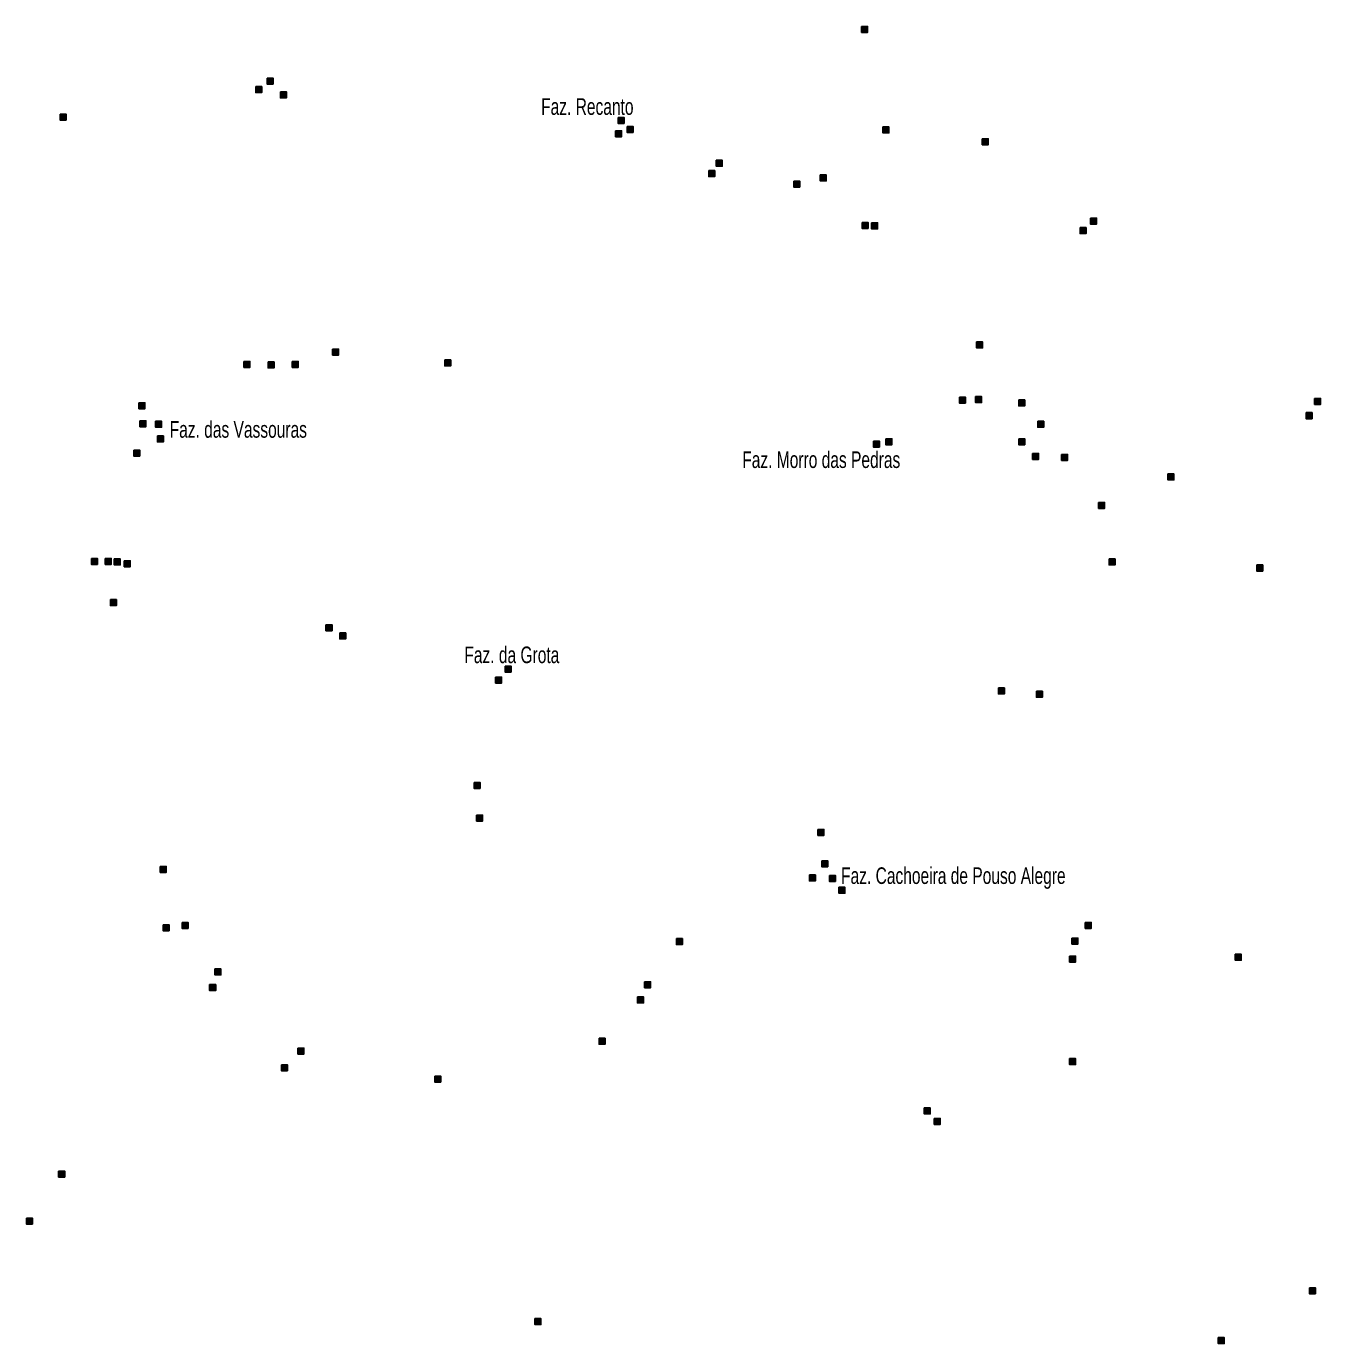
# Model space of a CAD drawing. Extents: x 447.8 to 473.9, y 7733.1 to 7760.8.
# Drawn here: x 461.4 to 467.64, y 7733.67 to 7740.03 of the extents above; entities that cross this region are included whole.
import ezdxf
from ezdxf.enums import TextEntityAlignment as Align

# ---------------------------------------------------------------- set-up
doc = ezdxf.new("R2010")
doc.units = 0
doc.header["$LTSCALE"] = 0.032
doc.layers.add('2', color=7, linetype='Continuous', lineweight=25)
doc.layers.add('61', color=7, linetype='Continuous')

msp = doc.modelspace()

# ---------------------------------------------------------------- hatches: boundary and pattern name
at = {"layer": '2'}
for points in [[(465.4271, 7740.0274), (465.4561, 7740.0274), (465.4561, 7739.9984), (465.4271, 7739.9984)], [(462.5065, 7739.7367), (462.5355, 7739.7367), (462.5355, 7739.7077), (462.5065, 7739.7077)], [(462.5615, 7739.7779), (462.5905, 7739.7779), (462.5905, 7739.7489), (462.5615, 7739.7489)], [(462.6256, 7739.7116), (462.6546, 7739.7116), (462.6546, 7739.6826), (462.6256, 7739.6826)], [(461.5635, 7739.604), (461.5925, 7739.604), (461.5925, 7739.575), (461.5635, 7739.575)], [(464.2529, 7739.588), (464.2819, 7739.588), (464.2819, 7739.559), (464.2529, 7739.559)], [(464.2964, 7739.5445), (464.3254, 7739.5445), (464.3254, 7739.5155), (464.2964, 7739.5155)], [(465.5301, 7739.5422), (465.5591, 7739.5422), (465.5591, 7739.5132), (465.5301, 7739.5132)], [(464.2415, 7739.5239), (464.2705, 7739.5239), (464.2705, 7739.4949), (464.2415, 7739.4949)], [(466.0085, 7739.485), (466.0375, 7739.485), (466.0375, 7739.456), (466.0085, 7739.456)], [(464.7267, 7739.382), (464.7557, 7739.382), (464.7557, 7739.353), (464.7267, 7739.353)], [(464.6901, 7739.3316), (464.7191, 7739.3316), (464.7191, 7739.3026), (464.6901, 7739.3026)], [(465.228, 7739.311), (465.257, 7739.311), (465.257, 7739.282), (465.228, 7739.282)], [(465.0998, 7739.2813), (465.1288, 7739.2813), (465.1288, 7739.2523), (465.0998, 7739.2523)], [(466.5303, 7739.1027), (466.5593, 7739.1027), (466.5593, 7739.0737), (466.5303, 7739.0737)], [(465.4294, 7739.0821), (465.4584, 7739.0821), (465.4584, 7739.0531), (465.4294, 7739.0531)], [(465.4752, 7739.0798), (465.5042, 7739.0798), (465.5042, 7739.0508), (465.4752, 7739.0508)], [(466.48, 7739.0569), (466.509, 7739.0569), (466.509, 7739.0279), (466.48, 7739.0279)], [(462.8773, 7738.471), (462.9063, 7738.471), (462.9063, 7738.442), (462.8773, 7738.442)], [(465.981, 7738.5053), (466.01, 7738.5053), (466.01, 7738.4763), (465.981, 7738.4763)], [(462.4493, 7738.4115), (462.4783, 7738.4115), (462.4783, 7738.3825), (462.4493, 7738.3825)], [(462.566, 7738.4092), (462.595, 7738.4092), (462.595, 7738.3802), (462.566, 7738.3802)], [(462.6828, 7738.4115), (462.7118, 7738.4115), (462.7118, 7738.3825), (462.6828, 7738.3825)], [(463.4175, 7738.4184), (463.4465, 7738.4184), (463.4465, 7738.3894), (463.4175, 7738.3894)], [(461.9435, 7738.2124), (461.9725, 7738.2124), (461.9725, 7738.1834), (461.9435, 7738.1834)], [(465.8986, 7738.2398), (465.9276, 7738.2398), (465.9276, 7738.2108), (465.8986, 7738.2108)], [(465.9764, 7738.2421), (466.0054, 7738.2421), (466.0054, 7738.2131), (465.9764, 7738.2131)], [(466.1847, 7738.2261), (466.2137, 7738.2261), (466.2137, 7738.1971), (466.1847, 7738.1971)], [(467.6107, 7738.233), (467.6397, 7738.233), (467.6397, 7738.204), (467.6107, 7738.204)], [(467.5695, 7738.1643), (467.5985, 7738.1643), (467.5985, 7738.1353), (467.5695, 7738.1353)], [(461.9481, 7738.1254), (461.9771, 7738.1254), (461.9771, 7738.0964), (461.9481, 7738.0964)], [(462.0236, 7738.1231), (462.0526, 7738.1231), (462.0526, 7738.0941), (462.0236, 7738.0941)], [(466.2763, 7738.1231), (466.3053, 7738.1231), (466.3053, 7738.0941), (466.2763, 7738.0941)], [(462.0327, 7738.0521), (462.0617, 7738.0521), (462.0617, 7738.0231), (462.0327, 7738.0231)], [(465.4843, 7738.027), (465.5133, 7738.027), (465.5133, 7737.998), (465.4843, 7737.998)], [(465.5438, 7738.0384), (465.5728, 7738.0384), (465.5728, 7738.0094), (465.5438, 7738.0094)], [(466.1847, 7738.0384), (466.2137, 7738.0384), (466.2137, 7738.0094), (466.1847, 7738.0094)], [(461.9183, 7737.9835), (461.9473, 7737.9835), (461.9473, 7737.9545), (461.9183, 7737.9545)], [(466.2511, 7737.9674), (466.2801, 7737.9674), (466.2801, 7737.9384), (466.2511, 7737.9384)], [(466.3907, 7737.9629), (466.4197, 7737.9629), (466.4197, 7737.9339), (466.3907, 7737.9339)], [(466.9034, 7737.869), (466.9324, 7737.869), (466.9324, 7737.84), (466.9034, 7737.84)], [(466.5693, 7737.7317), (466.5983, 7737.7317), (466.5983, 7737.7027), (466.5693, 7737.7027)], [(461.7146, 7737.4616), (461.7436, 7737.4616), (461.7436, 7737.4326), (461.7146, 7737.4326)], [(461.781, 7737.4616), (461.81, 7737.4616), (461.81, 7737.4326), (461.781, 7737.4326)], [(461.8245, 7737.4593), (461.8535, 7737.4593), (461.8535, 7737.4303), (461.8245, 7737.4303)], [(461.8725, 7737.4502), (461.9015, 7737.4502), (461.9015, 7737.4212), (461.8725, 7737.4212)], [(466.6196, 7737.4593), (466.6486, 7737.4593), (466.6486, 7737.4303), (466.6196, 7737.4303)], [(467.3314, 7737.4296), (467.3604, 7737.4296), (467.3604, 7737.4006), (467.3314, 7737.4006)], [(461.8061, 7737.2625), (461.8351, 7737.2625), (461.8351, 7737.2335), (461.8061, 7737.2335)], [(462.8453, 7737.1412), (462.8743, 7737.1412), (462.8743, 7737.1122), (462.8453, 7737.1122)], [(462.9117, 7737.1023), (462.9407, 7737.1023), (462.9407, 7737.0733), (462.9117, 7737.0733)], [(463.7082, 7736.942), (463.7372, 7736.942), (463.7372, 7736.913), (463.7082, 7736.913)], [(463.6624, 7736.8894), (463.6914, 7736.8894), (463.6914, 7736.8604), (463.6624, 7736.8604)], [(466.0863, 7736.8368), (466.1153, 7736.8368), (466.1153, 7736.8078), (466.0863, 7736.8078)], [(466.2694, 7736.8207), (466.2984, 7736.8207), (466.2984, 7736.7917), (466.2694, 7736.7917)], [(463.5594, 7736.3813), (463.5884, 7736.3813), (463.5884, 7736.3523), (463.5594, 7736.3523)], [(463.5709, 7736.2233), (463.5999, 7736.2233), (463.5999, 7736.1943), (463.5709, 7736.1943)], [(465.2165, 7736.1547), (465.2455, 7736.1547), (465.2455, 7736.1257), (465.2165, 7736.1257)], [(465.2349, 7736.0036), (465.2639, 7736.0036), (465.2639, 7735.9746), (465.2349, 7735.9746)], [(462.0465, 7735.9761), (462.0755, 7735.9761), (462.0755, 7735.9471), (462.0465, 7735.9471)], [(465.1753, 7735.9349), (465.2043, 7735.9349), (465.2043, 7735.9059), (465.1753, 7735.9059)], [(465.2715, 7735.9327), (465.3005, 7735.9327), (465.3005, 7735.9037), (465.2715, 7735.9037)], [(465.3173, 7735.8754), (465.3463, 7735.8754), (465.3463, 7735.8464), (465.3173, 7735.8464)], [(462.0602, 7735.6946), (462.0892, 7735.6946), (462.0892, 7735.6656), (462.0602, 7735.6656)], [(462.1518, 7735.7061), (462.1808, 7735.7061), (462.1808, 7735.6771), (462.1518, 7735.6771)], [(466.5052, 7735.7061), (466.5342, 7735.7061), (466.5342, 7735.6771), (466.5052, 7735.6771)], [(464.5345, 7735.6282), (464.5635, 7735.6282), (464.5635, 7735.5992), (464.5345, 7735.5992)], [(466.4411, 7735.6305), (466.4701, 7735.6305), (466.4701, 7735.6015), (466.4411, 7735.6015)], [(466.4296, 7735.5436), (466.4586, 7735.5436), (466.4586, 7735.5146), (466.4296, 7735.5146)], [(467.2284, 7735.5527), (467.2574, 7735.5527), (467.2574, 7735.5237), (467.2284, 7735.5237)], [(462.3097, 7735.4818), (462.3387, 7735.4818), (462.3387, 7735.4528), (462.3097, 7735.4528)], [(464.3811, 7735.42), (464.4101, 7735.42), (464.4101, 7735.391), (464.3811, 7735.391)], [(462.2845, 7735.4062), (462.3135, 7735.4062), (462.3135, 7735.3772), (462.2845, 7735.3772)], [(464.3468, 7735.3467), (464.3758, 7735.3467), (464.3758, 7735.3177), (464.3468, 7735.3177)], [(462.7102, 7735.0995), (462.7392, 7735.0995), (462.7392, 7735.0705), (462.7102, 7735.0705)], [(464.1614, 7735.1476), (464.1904, 7735.1476), (464.1904, 7735.1186), (464.1614, 7735.1186)], [(466.4296, 7735.0492), (466.4586, 7735.0492), (466.4586, 7735.0202), (466.4296, 7735.0202)], [(462.6301, 7735.0194), (462.6591, 7735.0194), (462.6591, 7734.9904), (462.6301, 7734.9904)], [(463.3694, 7734.9645), (463.3984, 7734.9645), (463.3984, 7734.9355), (463.3694, 7734.9355)], [(465.7292, 7734.8111), (465.7582, 7734.8111), (465.7582, 7734.7821), (465.7292, 7734.7821)], [(465.7773, 7734.7608), (465.8063, 7734.7608), (465.8063, 7734.7318), (465.7773, 7734.7318)], [(461.5567, 7734.5067), (461.5857, 7734.5067), (461.5857, 7734.4777), (461.5567, 7734.4777)], [(461.401, 7734.2801), (461.43, 7734.2801), (461.43, 7734.2511), (461.401, 7734.2511)], [(467.5855, 7733.9436), (467.6145, 7733.9436), (467.6145, 7733.9146), (467.5855, 7733.9146)], [(463.8524, 7733.7949), (463.8814, 7733.7949), (463.8814, 7733.7659), (463.8524, 7733.7659)], [(467.146, 7733.7033), (467.175, 7733.7033), (467.175, 7733.6743), (467.146, 7733.6743)]]:
    msp.add_hatch(color=256, dxfattribs=at).paths.add_polyline_path(points)

# ---------------------------------------------------------------- linework, layer by layer
for points in [[(465.4271, 7740.0274), (465.4561, 7740.0274), (465.4561, 7739.9984), (465.4271, 7739.9984)], [(462.5065, 7739.7367), (462.5355, 7739.7367), (462.5355, 7739.7077), (462.5065, 7739.7077)], [(462.5615, 7739.7779), (462.5905, 7739.7779), (462.5905, 7739.7489), (462.5615, 7739.7489)], [(462.6256, 7739.7116), (462.6546, 7739.7116), (462.6546, 7739.6826), (462.6256, 7739.6826)], [(461.5635, 7739.604), (461.5925, 7739.604), (461.5925, 7739.575), (461.5635, 7739.575)], [(464.2529, 7739.588), (464.2819, 7739.588), (464.2819, 7739.559), (464.2529, 7739.559)], [(464.2964, 7739.5445), (464.3254, 7739.5445), (464.3254, 7739.5155), (464.2964, 7739.5155)], [(465.5301, 7739.5422), (465.5591, 7739.5422), (465.5591, 7739.5132), (465.5301, 7739.5132)], [(464.2415, 7739.5239), (464.2705, 7739.5239), (464.2705, 7739.4949), (464.2415, 7739.4949)], [(466.0085, 7739.485), (466.0375, 7739.485), (466.0375, 7739.456), (466.0085, 7739.456)], [(464.7267, 7739.382), (464.7557, 7739.382), (464.7557, 7739.353), (464.7267, 7739.353)], [(464.6901, 7739.3316), (464.7191, 7739.3316), (464.7191, 7739.3026), (464.6901, 7739.3026)], [(465.228, 7739.311), (465.257, 7739.311), (465.257, 7739.282), (465.228, 7739.282)], [(465.0998, 7739.2813), (465.1288, 7739.2813), (465.1288, 7739.2523), (465.0998, 7739.2523)], [(466.5303, 7739.1027), (466.5593, 7739.1027), (466.5593, 7739.0737), (466.5303, 7739.0737)], [(465.4294, 7739.0821), (465.4584, 7739.0821), (465.4584, 7739.0531), (465.4294, 7739.0531)], [(465.4752, 7739.0798), (465.5042, 7739.0798), (465.5042, 7739.0508), (465.4752, 7739.0508)], [(466.48, 7739.0569), (466.509, 7739.0569), (466.509, 7739.0279), (466.48, 7739.0279)], [(462.8773, 7738.471), (462.9063, 7738.471), (462.9063, 7738.442), (462.8773, 7738.442)], [(465.981, 7738.5053), (466.01, 7738.5053), (466.01, 7738.4763), (465.981, 7738.4763)], [(462.4493, 7738.4115), (462.4783, 7738.4115), (462.4783, 7738.3825), (462.4493, 7738.3825)], [(462.566, 7738.4092), (462.595, 7738.4092), (462.595, 7738.3802), (462.566, 7738.3802)], [(462.6828, 7738.4115), (462.7118, 7738.4115), (462.7118, 7738.3825), (462.6828, 7738.3825)], [(463.4175, 7738.4184), (463.4465, 7738.4184), (463.4465, 7738.3894), (463.4175, 7738.3894)], [(461.9435, 7738.2124), (461.9725, 7738.2124), (461.9725, 7738.1834), (461.9435, 7738.1834)], [(465.8986, 7738.2398), (465.9276, 7738.2398), (465.9276, 7738.2108), (465.8986, 7738.2108)], [(465.9764, 7738.2421), (466.0054, 7738.2421), (466.0054, 7738.2131), (465.9764, 7738.2131)], [(466.1847, 7738.2261), (466.2137, 7738.2261), (466.2137, 7738.1971), (466.1847, 7738.1971)], [(467.6107, 7738.233), (467.6397, 7738.233), (467.6397, 7738.204), (467.6107, 7738.204)], [(467.5695, 7738.1643), (467.5985, 7738.1643), (467.5985, 7738.1353), (467.5695, 7738.1353)], [(461.9481, 7738.1254), (461.9771, 7738.1254), (461.9771, 7738.0964), (461.9481, 7738.0964)], [(462.0236, 7738.1231), (462.0526, 7738.1231), (462.0526, 7738.0941), (462.0236, 7738.0941)], [(466.2763, 7738.1231), (466.3053, 7738.1231), (466.3053, 7738.0941), (466.2763, 7738.0941)], [(462.0327, 7738.0521), (462.0617, 7738.0521), (462.0617, 7738.0231), (462.0327, 7738.0231)], [(465.4843, 7738.027), (465.5133, 7738.027), (465.5133, 7737.998), (465.4843, 7737.998)], [(465.5438, 7738.0384), (465.5728, 7738.0384), (465.5728, 7738.0094), (465.5438, 7738.0094)], [(466.1847, 7738.0384), (466.2137, 7738.0384), (466.2137, 7738.0094), (466.1847, 7738.0094)], [(461.9183, 7737.9835), (461.9473, 7737.9835), (461.9473, 7737.9545), (461.9183, 7737.9545)], [(466.2511, 7737.9674), (466.2801, 7737.9674), (466.2801, 7737.9384), (466.2511, 7737.9384)], [(466.3907, 7737.9629), (466.4197, 7737.9629), (466.4197, 7737.9339), (466.3907, 7737.9339)], [(466.9034, 7737.869), (466.9324, 7737.869), (466.9324, 7737.84), (466.9034, 7737.84)], [(466.5693, 7737.7317), (466.5983, 7737.7317), (466.5983, 7737.7027), (466.5693, 7737.7027)], [(461.7146, 7737.4616), (461.7436, 7737.4616), (461.7436, 7737.4326), (461.7146, 7737.4326)], [(461.781, 7737.4616), (461.81, 7737.4616), (461.81, 7737.4326), (461.781, 7737.4326)], [(461.8245, 7737.4593), (461.8535, 7737.4593), (461.8535, 7737.4303), (461.8245, 7737.4303)], [(461.8725, 7737.4502), (461.9015, 7737.4502), (461.9015, 7737.4212), (461.8725, 7737.4212)], [(466.6196, 7737.4593), (466.6486, 7737.4593), (466.6486, 7737.4303), (466.6196, 7737.4303)], [(467.3314, 7737.4296), (467.3604, 7737.4296), (467.3604, 7737.4006), (467.3314, 7737.4006)], [(461.8061, 7737.2625), (461.8351, 7737.2625), (461.8351, 7737.2335), (461.8061, 7737.2335)], [(462.8453, 7737.1412), (462.8743, 7737.1412), (462.8743, 7737.1122), (462.8453, 7737.1122)], [(462.9117, 7737.1023), (462.9407, 7737.1023), (462.9407, 7737.0733), (462.9117, 7737.0733)], [(463.7082, 7736.942), (463.7372, 7736.942), (463.7372, 7736.913), (463.7082, 7736.913)], [(463.6624, 7736.8894), (463.6914, 7736.8894), (463.6914, 7736.8604), (463.6624, 7736.8604)], [(466.0863, 7736.8368), (466.1153, 7736.8368), (466.1153, 7736.8078), (466.0863, 7736.8078)], [(466.2694, 7736.8207), (466.2984, 7736.8207), (466.2984, 7736.7917), (466.2694, 7736.7917)], [(463.5594, 7736.3813), (463.5884, 7736.3813), (463.5884, 7736.3523), (463.5594, 7736.3523)], [(463.5709, 7736.2233), (463.5999, 7736.2233), (463.5999, 7736.1943), (463.5709, 7736.1943)], [(465.2165, 7736.1547), (465.2455, 7736.1547), (465.2455, 7736.1257), (465.2165, 7736.1257)], [(465.2349, 7736.0036), (465.2639, 7736.0036), (465.2639, 7735.9746), (465.2349, 7735.9746)], [(462.0465, 7735.9761), (462.0755, 7735.9761), (462.0755, 7735.9471), (462.0465, 7735.9471)], [(465.1753, 7735.9349), (465.2043, 7735.9349), (465.2043, 7735.9059), (465.1753, 7735.9059)], [(465.2715, 7735.9327), (465.3005, 7735.9327), (465.3005, 7735.9037), (465.2715, 7735.9037)], [(465.3173, 7735.8754), (465.3463, 7735.8754), (465.3463, 7735.8464), (465.3173, 7735.8464)], [(462.0602, 7735.6946), (462.0892, 7735.6946), (462.0892, 7735.6656), (462.0602, 7735.6656)], [(462.1518, 7735.7061), (462.1808, 7735.7061), (462.1808, 7735.6771), (462.1518, 7735.6771)], [(466.5052, 7735.7061), (466.5342, 7735.7061), (466.5342, 7735.6771), (466.5052, 7735.6771)], [(464.5345, 7735.6282), (464.5635, 7735.6282), (464.5635, 7735.5992), (464.5345, 7735.5992)], [(466.4411, 7735.6305), (466.4701, 7735.6305), (466.4701, 7735.6015), (466.4411, 7735.6015)], [(466.4296, 7735.5436), (466.4586, 7735.5436), (466.4586, 7735.5146), (466.4296, 7735.5146)], [(467.2284, 7735.5527), (467.2574, 7735.5527), (467.2574, 7735.5237), (467.2284, 7735.5237)], [(462.3097, 7735.4818), (462.3387, 7735.4818), (462.3387, 7735.4528), (462.3097, 7735.4528)], [(464.3811, 7735.42), (464.4101, 7735.42), (464.4101, 7735.391), (464.3811, 7735.391)], [(462.2845, 7735.4062), (462.3135, 7735.4062), (462.3135, 7735.3772), (462.2845, 7735.3772)], [(464.3468, 7735.3467), (464.3758, 7735.3467), (464.3758, 7735.3177), (464.3468, 7735.3177)], [(462.7102, 7735.0995), (462.7392, 7735.0995), (462.7392, 7735.0705), (462.7102, 7735.0705)], [(464.1614, 7735.1476), (464.1904, 7735.1476), (464.1904, 7735.1186), (464.1614, 7735.1186)], [(466.4296, 7735.0492), (466.4586, 7735.0492), (466.4586, 7735.0202), (466.4296, 7735.0202)], [(462.6301, 7735.0194), (462.6591, 7735.0194), (462.6591, 7734.9904), (462.6301, 7734.9904)], [(463.3694, 7734.9645), (463.3984, 7734.9645), (463.3984, 7734.9355), (463.3694, 7734.9355)], [(465.7292, 7734.8111), (465.7582, 7734.8111), (465.7582, 7734.7821), (465.7292, 7734.7821)], [(465.7773, 7734.7608), (465.8063, 7734.7608), (465.8063, 7734.7318), (465.7773, 7734.7318)], [(461.5567, 7734.5067), (461.5857, 7734.5067), (461.5857, 7734.4777), (461.5567, 7734.4777)], [(461.401, 7734.2801), (461.43, 7734.2801), (461.43, 7734.2511), (461.401, 7734.2511)], [(467.5855, 7733.9436), (467.6145, 7733.9436), (467.6145, 7733.9146), (467.5855, 7733.9146)], [(463.8524, 7733.7949), (463.8814, 7733.7949), (463.8814, 7733.7659), (463.8524, 7733.7659)], [(467.146, 7733.7033), (467.175, 7733.7033), (467.175, 7733.6743), (467.146, 7733.6743)]]:
    msp.add_lwpolyline(points, close=True, dxfattribs=at)

# ---------------------------------------------------------------- texts
at = {"layer": '61', "width": 0.7}
for s, p in [('Faz. Recanto', (464.3277, 7739.6004)), ('Faz. Morro das Pedras', (465.6134, 7737.8975)), ('Faz. da Grota', (463.97, 7736.9563))]:
    msp.add_text(s, height=0.08, dxfattribs=at).set_placement(p, align=Align.RIGHT)
for s, p in [('Faz. das Vassouras', (462.0917, 7738.0434)), ('Faz. Cachoeira de Pouso Alegre', (465.3281, 7735.8914))]:
    msp.add_text(s, height=0.08, dxfattribs=at).set_placement(p)

doc.saveas('drawing.dxf')
